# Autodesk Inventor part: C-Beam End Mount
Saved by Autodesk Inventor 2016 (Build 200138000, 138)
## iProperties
Created: 2016-01
Part Number: C-Beam End Mount
Material: Generic
Document SubType Name: Modeling
Designer: John
Density: 1 g/cm^3
Appearance: Default
Author: John
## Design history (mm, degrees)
feature "CUT-EXTRUDE2"
body "Solid1"
